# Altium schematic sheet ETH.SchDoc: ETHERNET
size A4; Author: Daniela Catanzaro; CompanyName: Arduino srl; DocumentNumber: ASX00055; SheetNumber: 9; SheetTotal: 10; RevAuthor: Daniela Catanzaro
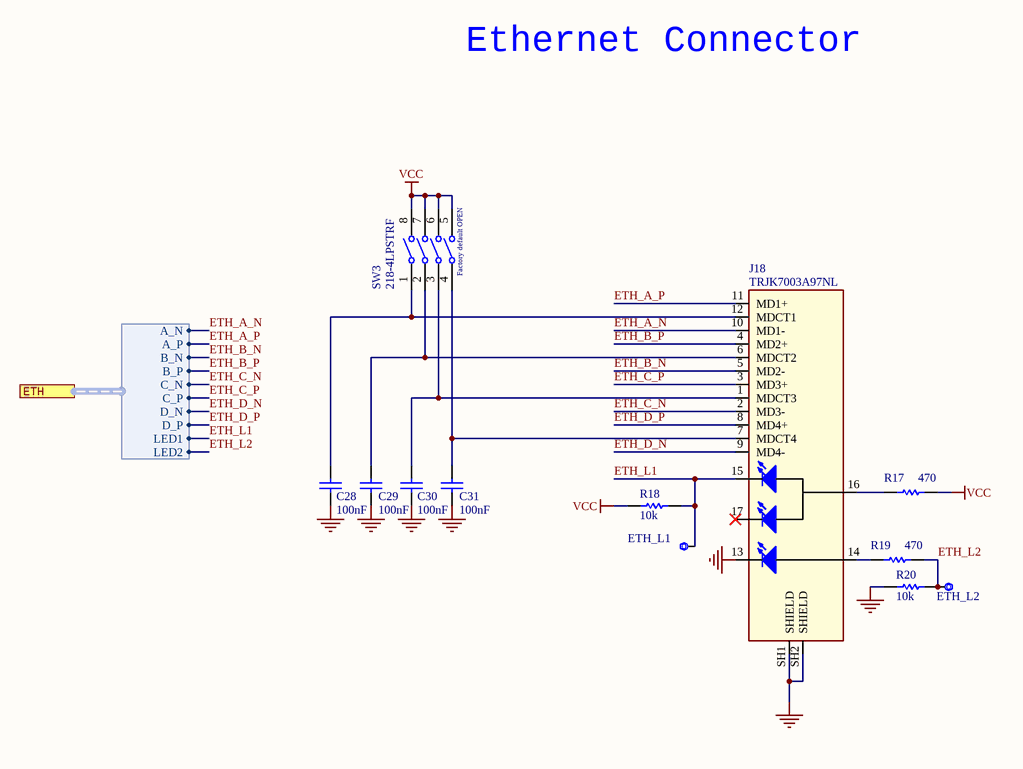
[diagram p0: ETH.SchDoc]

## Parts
C28  value 100nF  [CAP-0603]  (hidden comment: 0603B104K500CT)
C29  value 100nF  [CAP-0603]  (hidden comment: 0603B104K500CT)
C30  value 100nF  [CAP-0603]  (hidden comment: 0603B104K500CT)
C31  value 100nF  [CAP-0603]  (hidden comment: 0603B104K500CT)
ETH_L1  Test point 1.00mm  [TP-1.00MM]  (value not drawn)  (no BOM)
ETH_L2  Test point 1.00mm  [TP-1.00MM]  (value not drawn)  (no BOM)
J18  TRJK7003A97NL  [TRJK0071AWNL -Footprint-2]
R17  value 470  [RES-0402]  (hidden comment: CRCW0402470RJNED)
R18  value 10k  [RES-0402]  (hidden comment: CRCW040210K0FKED)
R19  value 470  [RES-0402]  (hidden comment: CRCW0402470RJNED)
R20  value 10k  [RES-0402]  (hidden comment: CRCW040210K0FKED)
SW3  218-4LPSTRF  [CTS-218-4LPST_V]

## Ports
ETH (harness ETH)

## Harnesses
ETH: A_N, A_P, B_N, B_P, C_N, C_P, D_N, D_P, LED1, LED2

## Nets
GND: C28.2 C29.2 C30.2 C31.2 J18.13 J18.SH1(SHIELD) J18.SH2(SHIELD) R20.2
VCC: R17.2 R18.2 SW3.5 SW3.6 SW3.7 SW3.8
ETH_A_N: J18.10(MD1-) ; port ETH.A_N
ETH_A_P: J18.11(MD1+) ; port ETH.A_P
ETH_B_N: J18.5(MD2-) ; port ETH.B_N
ETH_B_P: J18.4(MD2+) ; port ETH.B_P
ETH_C_N: J18.2(MD3-) ; port ETH.C_N
ETH_C_P: J18.3(MD3+) ; port ETH.C_P
ETH_D_N: J18.9(MD4-) ; port ETH.D_N
ETH_D_P: J18.8(MD4+) ; port ETH.D_P
ETH_L1: ETH_L1.X J18.15 R18.1 ; port ETH.LED1
ETH_L2: ETH_L2.X R19.2 R20.1 ; port ETH.LED2
NetC28_1: C28.1 J18.12(MDCT1) SW3.1
NetC29_1: C29.1 J18.6(MDCT2) SW3.2
NetC30_1: C30.1 J18.1(MDCT3) SW3.3
NetC31_1: C31.1 J18.7(MDCT4) SW3.4
NetJ18_14: J18.14 R19.1
NetJ18_16: J18.16 R17.1

Not connected (* = marked no-connect by the designer): J18 17*

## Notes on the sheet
- Ethernet Connector

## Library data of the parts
C28-C31 = C0043-A.14: CAP CHIP 0603 100nF 10% 50V X7R; Manufacturer: Walsin; Code Arduino: 0015
ETH_L1 ETH_L2 = UT0013-A.6: Manufacturer: This is not a component
J18 = J0027-A.7: CONN ETHERNET 1GIGABIT; Manufacturer: TRXCOM; Code Arduino: A5565
R17 R19 = R0055-A.25: RES CHIP 0402 470R 5% 1/16W; Manufacturer: Vishay; Power: 62.5mW; Code Arduino: R0055; Temperature coefficient: 200ppm
R18 R20 = R0003-A.24: RES CHIP 0402 10k 1% 1/16W; Manufacturer: Vishay; Code Arduino: 0136; Power: 62.5mW; Temperature coefficient: 100ppm
SW3 = S0033-A.1: SWITCH DIP 4 positions NORMALLY OPEN; Manufacturer: CTS Corporation; Voltage Rating (DC): 24V; Number of Positions: 4; Actuator Type: Slide (Standard); Washable: Yes; Current Rating: 25mA; Contact Resistance: 100mR; Electrical Life: 1000Cycles; Throw Configuration: SPST; Pitch: 0.05inch; Code Arduino: S0033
